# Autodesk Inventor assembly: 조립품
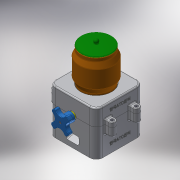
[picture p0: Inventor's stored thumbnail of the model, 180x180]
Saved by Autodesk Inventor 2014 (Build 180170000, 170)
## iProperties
Created: 2018-01
Part Number: 조립품
Document SubType Name: Assembly
Designer: user
Author: user
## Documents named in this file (9)
- C:\Users\user\Desktop\480108V1014\조립품.iam
- C:\Users\user\Desktop\480108V1014\본체.ipt
- C:\Users\user\Desktop\480108V1014\본체커버.ipt
- C:\Users\user\Desktop\480108V1014\볼트 M3x12.ipt
- C:\Users\user\Desktop\480108V1014\볼트 M4x12.ipt
- C:\Users\user\Desktop\480108V1014\용기.ipt
- C:\Users\user\Desktop\480108V1014\용기캡.ipt
- C:\Users\user\Desktop\480108V1014\핸들.ipt
- C:\Users\user\Desktop\480108V1014\핸들축.ipt
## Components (2 placed, 2 different names)
1. 핸들:1 — Mate:1, Mate:2, Mate:3, Insert:1
2. 핸들축:1 — Mate:1, Mate:2, Mate:3, Insert:6
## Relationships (5: Mate 3, Insert 2)
- Mate:1: 핸들:1 ↔ 핸들축:1
- Mate:2: 핸들:1 ↔ 핸들축:1
- Mate:3: 핸들:1 ↔ 핸들축:1
- Insert:1: 핸들:1
- Insert:6: 핸들축:1
